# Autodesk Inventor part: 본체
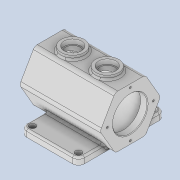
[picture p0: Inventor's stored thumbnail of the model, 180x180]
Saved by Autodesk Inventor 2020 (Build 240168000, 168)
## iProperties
Created: 2021-06
Part Number: 본체
Material: 일반
Document SubType Name: Modeling
Designer: MIRAE
Density: 1 g/cm^3
Appearance: 기본값
Mass: 553.742 g
Surface Area: 1103.82 cm^2
Volume: 553.742 cm^3
Author: MIRAE
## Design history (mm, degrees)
sketch "스케치3"
  geometry: L1 (50, -75)-(-50, -75); L2 (-50, -75)-(-50, 75); L3 (-50, 75)-(50, 75); L4 (50, 75)-(50, -75); L5 (50, -75)-(-50, 75); L6 (-50, -75)-(50, 75); 1 further point
  constraints: 12 end point, 2 midpoint, 2 parallel, 1 horizontal, 1 perpendicular
  dimensions: "d6" = 100 distance of L2.end L3.end; "d7" = 150 distance of L1.end L2.end
extrude "돌출2" new body sketch "스케치3" distance "d8" = 12; taper "d9" = 0 deg
node "작업 평면1"
sketch "스케치4" dims "d11" = 105
  geometry: L1 (12, 150)-(12, 0) reference; L2 (-38, 127.5)-(7.466, 101.25); L3 (7.466, 101.25)-(7.466, 48.75); L4 (7.466, 48.75)-(-38, 22.5); L5 (-38, 22.5)-(-83.466, 48.75); L6 (-83.466, 48.75)-(-83.466, 101.25); L7 (-83.466, 101.25)-(-38, 127.5); 3 further points
  constraints: 12 end point, 1 coincident, 1 horizontal alignment, 1 vertical, 1 vertical alignment, 15 other
  dimensions: "d12" = 50 distance from line of L1 point (-38, 75)
extrude "돌출3" join sketch "스케치4" distance "d13" = 140; taper "d14" = 0 deg
sketch "스케치5"
  geometry: L1 (75, -38)-(75, -83.466) reference; L2 (75, -38)-(-65, -38) reference; L3 (-65, -83.466)-(-65, -38) reference; L4 (75, -83.466)-(-65, -83.466) reference; L5 (-65, -38)-(75, -38); L6 (-65, -68)-(-53, -68); L7 (-53, -68)-(-53, -75.5); L8 (-53, -75.5)-(63, -75.5); L9 (63, -75.5)-(63, -68); L10 (63, -68)-(75, -68); L11 (75, -68)-(75, -38); L12 (-65, -68)-(-65, -38); 1 further point
  constraints: 16 end point, 3 collinear, 3 perpendicular, 2 point on line, 1 horizontal, 1 vertical
  dimensions: "d15" = 60 diameter of L10 L2; "d16" = 60 diameter of L6 L2; "d17" = 75 diameter of L8 L2; "d18" = 12 distance between parallel lines of L7 L3; "d19" = 12 distance between parallel lines of L1 L9
revolve "회전1" sketch "스케치5" stored, may be unused: angle "d20" = 90 deg
fillet "모깎기1" dims "d21" = 5
node "작업 평면4"
sketch "스케치8"
  geometry: L1 (75, 26.25)-(75, -26.25) reference; C1 r 20 at (-25, 0); C2 r 20 at (35, 0); 1 further point
  constraints: 2 centre point, 2 horizontal alignment
  dimensions: "d30" = 40 diameter of C1; "d31" = 40 diameter of C2; "d32" = 60 distance of C2.centre C1.centre; "d34" = 40 distance from line of C2.centre L1
extrude "돌출5" join sketch "스케치8" stored distance "d35" = 140; taper "d36" = 0 deg
sketch "스케치9"
  geometry: C1 r 20 at (-25, 0) reference; C2 r 20 at (35, 0) reference; 3 further points
  constraints: 2 coincident
hole "구멍1" sketch "스케치9" at (35, 0), (-25, 0) diameter "d37" = 25; stored, may be unused: countersink angle "d41" = 90 deg, drill point angle "d43" = 118 deg; dims "d38" = 6, "d39" = 30, "d40" = 8, "d42" = 8
sketch "스케치10" dims "d44" = 80
  geometry: L1 (38, 75)-(78, 75); C1 r 32.5 at (38, 75) reference; 2 further points
  constraints: 2 coincident, 2 end point, 1 horizontal, 1 horizontal alignment, 2 other
hole "구멍2" sketch "스케치10" at (78, 75) diameter "d45" = 3.45873; stored, may be unused: countersink angle "d49" = 90 deg, drill point angle "d51" = 118 deg; dims "d46" = 8, "d47" = 30, "d48" = 8, "d50" = 10
sketch "스케치11"
  geometry: L1 (-38, 75)-(-78, 75); L2 (-38, 75)-(-66.284, 46.716); C1 r 30 at (-38, 75) reference; A1 r 40 centre (-38, 75) between (-78, 75) and (-66.284, 46.716); 2 further points
  constraints: 4 end point, 2 coincident, 2 point on circle, 1 centre point, 1 horizontal
  dimensions: "d55" = 80 diameter of A1; "d56" = 45 deg angle of L1 L2
hole "구멍3" sketch "스케치11" at (-66.284, 46.716) diameter "d57" = 3.45873; stored, may be unused: countersink angle "d61" = 90 deg, drill point angle "d63" = 118 deg; dims "d58" = 8, "d59" = 30, "d60" = 8, "d62" = 10
fillet "모깎기2" dims "d67" = 10
fillet "모깎기3" dims "d68" = 3
sketch "스케치12"
  geometry: A1 r 10 centre (-40, -65) between (-50, -65) and (-40, -75) reference; A2 r 10 centre (40, -65) between (40, -75) and (50, -65) reference; A3 r 10 centre (40, 65) between (50, 65) and (40, 75) reference; A4 r 10 centre (-40, 65) between (-40, 75) and (-50, 65) reference; 5 further points
  constraints: 4 coincident
hole "구멍4" sketch "스케치12" at (-40, -65), (40, -65), (40, 65), (-40, 65) diameter "d69" = 11; stored, may be unused: countersink angle "d73" = 90 deg, drill point angle "d75" = 118 deg; dims "d70" = 8, "d71" = 30, "d72" = 8, "d74" = 10
fillet "모깎기4" dims "d76" = 8
fillet "모깎기5" dims "d77" = 3
fillet "모깎기6" dims "d78" = 3
sketch "스케치13"
  geometry: L1 (-20.739, -57.998)-(20.739, -57.998); L2 (20.739, -57.998)-(20.739, -64.002); L3 (20.739, -64.002)-(-20.739, -64.002); L4 (-20.739, -64.002)-(-20.739, -57.998); L5 (-20.739, -57.998)-(20.739, -64.002); L6 (50, -65)-(50, -32.293) reference; L7 (-40, -75)-(40, -75) reference; 2 further points
  constraints: 2 end point, 1 midpoint, 2 other
  dimensions: "d79" = 50 distance from line of point (0, -61) L6; "d80" = 14 distance from line of L7 point (0, -61)
feature "엠보싱1" sketch "스케치13" dims "d6" = 100, "d7" = 150, "d81" = 0.5, "d82" = 0
chamfer "모따기1" distance "d83" = 1; stored, may be unused: second distance "d84" = 2, angle "d85" = 45 deg
node "솔리드2"
pattern_circular "원형 패턴1" dims angle "d53" = 360 deg
pattern_circular "원형 패턴2" dims angle "d65" = 360 deg
node "투영된 루프1"
node "투영된 루프3"
node "투영된 루프4"
feature "A9D066F2-1C7D-4E18-AEED-F7BC21143FA4" dims "d69" = 11, "d70" = 8, "d71" = 30, "d72" = 8, "d73" = 90 deg, "d74" = 10, "d75" = 118 deg
other parameters: "d10" = 25, "d29" = -102.5
